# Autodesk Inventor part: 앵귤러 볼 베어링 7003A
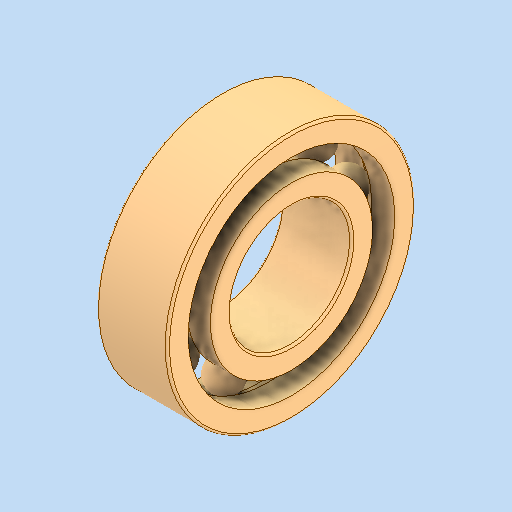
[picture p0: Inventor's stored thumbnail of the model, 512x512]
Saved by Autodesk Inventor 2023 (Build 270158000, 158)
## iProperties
Created: 2024-11
Part Number: 앵귤러 볼 베어링 7003A
Material: 강철, 연강
Description: 앵귤러 콘택트 볼 베어링
Document SubType Name: Modeling
Designer: asung
Density: 7.85 g/cm^3
Appearance: 기본값
Author: jhkim
Sending System: Autodesk Inventor 2025
Preprocessor: ST-DEVELOPER v20
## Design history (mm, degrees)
node "앵귤러 볼 베어링 7003A1"
node "솔리드1"
node "솔리드2"
node "솔리드3"
node "솔리드4"
node "솔리드5"
node "솔리드6"
node "솔리드7"
node "솔리드8"
node "솔리드9"
node "솔리드10"
node "솔리드11"
body "Solid1"
node "Solid1:1"
node "Solid1:2"
node "Solid1:3"
node "Solid1:4"
node "Solid1:5"
node "Solid1:6"
node "Solid1:7"
node "Solid1:8"
node "Solid1:9"
node "Solid1:10"
